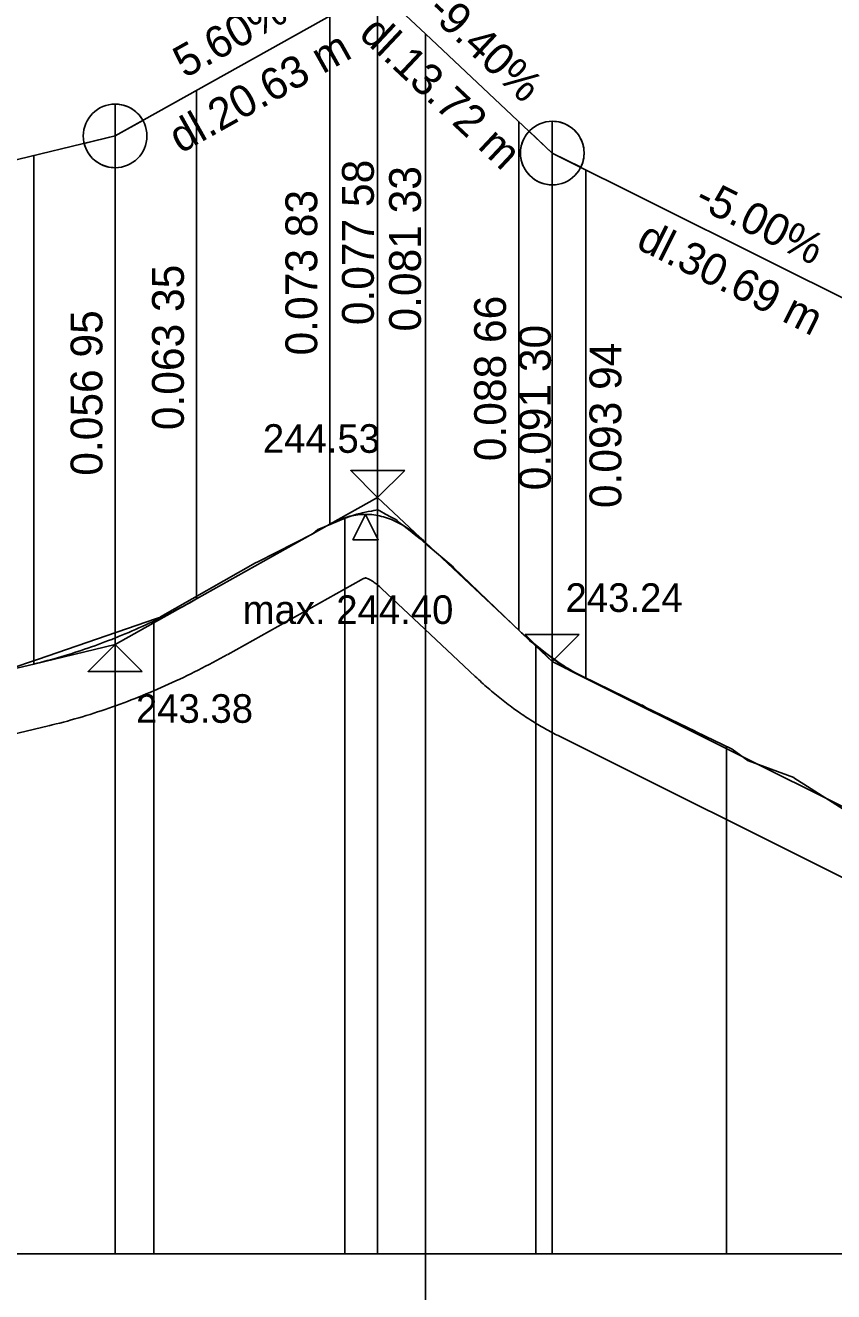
# Model space of a CAD drawing. Extents: x -598463 to -597973, y -1203201 to -1202904.
# Drawn here: x -598289.3 to -598225.8, y -1203056 to -1202956.4 of the extents above; entities that cross this region are included whole.
import ezdxf

# ---------------------------------------------------------------- set-up
doc = ezdxf.new("R2010")
doc.units = 0
for name, color, linetype in [('geom_Pomoc', 7, 'Continuous'), ('profil_popis', 7, 'Continuous'), ('profil_popis_niveleta', 7, 'Continuous'), ('rez_teren', 7, 'Continuous')]:
    doc.layers.add(name, color=color, linetype=linetype)

msp = doc.modelspace()

# ---------------------------------------------------------------- linework, layer by layer
at = {"layer": 'geom_Pomoc'}
for p, q in [((-598257.882, -1202997.029), (-598257.883, -1203138.847)), ((-598339.213, -1203052.987), (-598207.733, -1203052.987))]:
    msp.add_line(p, q, dxfattribs=at)
at = {"layer": 'profil_popis'}
for p, q in [((-598261.632, -1202953.504), (-598261.632, -1203052.987)), ((-598282.262, -1202965.057), (-598282.262, -1203052.987))]:
    msp.add_line(p, q, dxfattribs=at)
for points in [[(-598264.213, -1202995.131), (-598264.213, -1203052.987)], [(-598279.213, -1203003.087), (-598279.213, -1203052.987)], [(-598249.213, -1203005.1), (-598249.213, -1203052.987)], [(-598247.908, -1203005.1), (-598247.908, -1203052.987)], [(-598234.213, -1203013.077), (-598234.213, -1203052.987)]]:
    msp.add_lwpolyline(points, dxfattribs=at)
at = {"layer": 'profil_popis_niveleta'}
for p, q in [((-598282.262, -1202965.057), (-598261.632, -1202953.504)), ((-598261.632, -1202953.504), (-598261.632, -1202993.504)), ((-598261.632, -1202953.504), (-598257.882, -1202957.029)), ((-598265.382, -1202995.604), (-598265.382, -1202955.604)), ((-598257.882, -1202997.029), (-598257.882, -1202957.029)), ((-598257.882, -1202957.029), (-598247.908, -1202966.404)), ((-598275.862, -1203001.473), (-598275.862, -1202961.473)), ((-598250.548, -1203003.922), (-598250.548, -1202963.922)), ((-598316.917, -1202973.374), (-598282.262, -1202965.057)), ((-598282.262, -1202965.057), (-598282.262, -1203005.057)), ((-598288.662, -1203006.593), (-598288.662, -1202966.593)), ((-598247.908, -1202966.404), (-598247.908, -1203006.404)), ((-598247.908, -1202966.404), (-598217.22, -1202981.748)), ((-598245.268, -1203007.724), (-598245.268, -1202967.724)), ((-598265.382, -1202995.604), (-598261.632, -1202993.504)), ((-598261.632, -1202993.504), (-598257.882, -1202997.029)), ((-598275.862, -1203001.473), (-598265.382, -1202995.604)), ((-598257.882, -1202997.029), (-598250.548, -1203003.922)), ((-598273.419, -1203005.835), (-598262.939, -1202999.966)), ((-598261.306, -1203000.672), (-598258.361, -1203003.441)), ((-598282.262, -1203005.057), (-598275.862, -1203001.473)), ((-598258.361, -1203003.441), (-598253.973, -1203007.565)), ((-598250.548, -1203003.922), (-598247.908, -1203006.404)), ((-598288.662, -1203006.593), (-598282.262, -1203005.057)), ((-598301.717, -1203009.726), (-598288.662, -1203006.593)), ((-598247.908, -1203006.404), (-598245.268, -1203007.724)), ((-598245.268, -1203007.724), (-598221.12, -1203019.798)), ((-598300.551, -1203014.588), (-598287.495, -1203011.455)), ((-598247.504, -1203012.196), (-598223.356, -1203024.27))]:
    msp.add_line(p, q, dxfattribs=at)
for points in [[(-598282.262, -1202965.057), (-598282.262, -1202962.557), (-598282.102, -1202962.562), (-598281.942, -1202962.577), (-598281.784, -1202962.603), (-598281.628, -1202962.638), (-598281.474, -1202962.684), (-598281.324, -1202962.739), (-598281.177, -1202962.804), (-598281.035, -1202962.878), (-598280.898, -1202962.961), (-598280.767, -1202963.053), (-598280.641, -1202963.153), (-598280.523, -1202963.261), (-598280.411, -1202963.376), (-598280.307, -1202963.498), (-598280.212, -1202963.626), (-598280.124, -1202963.761), (-598280.081, -1202963.835), (-598282.262, -1202965.057), (-598282.262, -1202967.557), (-598282.422, -1202967.551), (-598282.582, -1202967.536), (-598282.74, -1202967.511), (-598282.896, -1202967.475), (-598283.05, -1202967.429), (-598283.2, -1202967.374), (-598283.347, -1202967.309), (-598283.489, -1202967.235), (-598283.626, -1202967.152), (-598283.757, -1202967.06), (-598283.883, -1202966.96), (-598284.001, -1202966.852), (-598284.113, -1202966.737), (-598284.217, -1202966.615), (-598284.312, -1202966.487), (-598284.4, -1202966.353), (-598284.479, -1202966.213), (-598284.548, -1202966.069), (-598284.608, -1202965.92), (-598284.659, -1202965.768), (-598284.693, -1202965.64)], [(-598247.908, -1202966.404), (-598247.908, -1202963.904), (-598247.748, -1202963.909), (-598247.588, -1202963.924), (-598247.43, -1202963.95), (-598247.274, -1202963.986), (-598247.12, -1202964.031), (-598246.97, -1202964.086), (-598246.823, -1202964.151), (-598246.681, -1202964.225), (-598246.544, -1202964.309), (-598246.413, -1202964.4), (-598246.287, -1202964.5), (-598246.169, -1202964.608), (-598246.057, -1202964.723), (-598245.953, -1202964.845), (-598245.858, -1202964.973), (-598245.77, -1202965.108), (-598245.692, -1202965.247), (-598245.622, -1202965.392), (-598245.562, -1202965.54), (-598245.511, -1202965.692), (-598245.471, -1202965.847), (-598245.44, -1202966.005), (-598245.42, -1202966.164), (-598245.409, -1202966.324), (-598245.409, -1202966.484), (-598245.42, -1202966.644), (-598245.44, -1202966.803), (-598245.471, -1202966.96), (-598245.511, -1202967.115), (-598245.562, -1202967.267), (-598245.622, -1202967.416), (-598245.672, -1202967.522), (-598247.908, -1202966.404), (-598247.908, -1202968.904), (-598248.068, -1202968.899), (-598248.228, -1202968.883), (-598248.386, -1202968.858), (-598248.542, -1202968.822), (-598248.696, -1202968.776), (-598248.846, -1202968.721), (-598248.993, -1202968.656), (-598249.135, -1202968.582), (-598249.272, -1202968.499), (-598249.403, -1202968.407), (-598249.529, -1202968.307), (-598249.647, -1202968.2), (-598249.759, -1202968.085), (-598249.863, -1202967.963), (-598249.958, -1202967.834), (-598250.046, -1202967.7), (-598250.125, -1202967.56), (-598250.194, -1202967.416), (-598250.254, -1202967.267), (-598250.305, -1202967.115), (-598250.345, -1202966.96), (-598250.376, -1202966.803), (-598250.397, -1202966.644), (-598250.407, -1202966.484), (-598250.407, -1202966.324), (-598250.397, -1202966.164), (-598250.376, -1202966.005), (-598250.345, -1202965.847), (-598250.305, -1202965.692), (-598250.254, -1202965.54), (-598250.194, -1202965.392), (-598250.125, -1202965.247), (-598250.046, -1202965.108), (-598249.958, -1202964.973), (-598249.863, -1202964.845), (-598249.759, -1202964.723), (-598249.73, -1202964.692)], [(-598262.582, -1202994.819), (-598263.582, -1202996.819), (-598261.582, -1202996.819)]]:
    msp.add_lwpolyline(points, close=True, dxfattribs=at)
for points in [[(-598261.632, -1202993.504), (-598263.753, -1202991.382), (-598259.51, -1202991.382)], [(-598259.51, -1202991.382), (-598261.632, -1202993.504)], [(-598265.382, -1202995.604), (-598265.225, -1202995.519), (-598265.069, -1202995.438), (-598264.913, -1202995.363), (-598264.757, -1202995.293), (-598264.6, -1202995.227), (-598264.444, -1202995.166), (-598264.288, -1202995.111), (-598264.132, -1202995.06), (-598263.975, -1202995.014), (-598263.819, -1202994.973), (-598263.663, -1202994.937), (-598263.507, -1202994.905), (-598263.35, -1202994.879), (-598263.194, -1202994.857), (-598263.038, -1202994.84), (-598262.882, -1202994.829), (-598262.725, -1202994.822), (-598262.569, -1202994.82), (-598262.413, -1202994.822), (-598262.257, -1202994.83), (-598262.1, -1202994.843), (-598261.944, -1202994.86), (-598261.788, -1202994.883), (-598261.475, -1202994.942), (-598261.319, -1202994.979), (-598261.163, -1202995.021), (-598261.007, -1202995.068), (-598260.85, -1202995.119), (-598260.694, -1202995.176), (-598260.538, -1202995.237), (-598260.382, -1202995.304), (-598260.225, -1202995.375), (-598260.069, -1202995.451), (-598259.913, -1202995.532), (-598259.757, -1202995.618), (-598259.6, -1202995.708), (-598259.444, -1202995.804), (-598259.288, -1202995.904), (-598259.132, -1202996.01), (-598258.975, -1202996.12), (-598258.819, -1202996.235), (-598258.663, -1202996.355), (-598258.507, -1202996.48), (-598258.35, -1202996.61), (-598258.194, -1202996.745), (-598258.038, -1202996.884), (-598257.882, -1202997.029)], [(-598262.991, -1202999.995), (-598262.888, -1202999.939), (-598262.842, -1202999.915), (-598262.8, -1202999.895), (-598262.762, -1202999.878), (-598262.729, -1202999.864), (-598262.699, -1202999.853), (-598262.673, -1202999.843), (-598262.651, -1202999.836), (-598262.633, -1202999.831), (-598262.618, -1202999.827), (-598262.606, -1202999.824), (-598262.597, -1202999.822), (-598262.591, -1202999.821), (-598262.586, -1202999.821), (-598262.585, -1202999.821), (-598262.529, -1202999.831), (-598262.528, -1202999.832), (-598262.509, -1202999.837), (-598262.486, -1202999.845), (-598262.46, -1202999.854), (-598262.43, -1202999.866), (-598262.395, -1202999.881), (-598262.357, -1202999.898), (-598262.314, -1202999.919), (-598262.267, -1202999.943), (-598262.216, -1202999.971), (-598262.161, -1203000.003), (-598262.102, -1203000.04), (-598262.038, -1203000.08), (-598261.971, -1203000.126), (-598261.9, -1203000.176), (-598261.825, -1203000.231), (-598261.747, -1203000.291), (-598261.665, -1203000.356), (-598261.58, -1203000.427), (-598261.492, -1203000.503), (-598261.4, -1203000.585), (-598261.276, -1203000.7)], [(-598288.662, -1203006.593), (-598288.395, -1203006.528), (-598288.129, -1203006.461), (-598287.862, -1203006.393), (-598287.595, -1203006.322), (-598287.329, -1203006.25), (-598287.062, -1203006.177), (-598286.795, -1203006.101), (-598286.529, -1203006.024), (-598286.262, -1203005.945), (-598285.995, -1203005.864), (-598285.729, -1203005.781), (-598285.462, -1203005.697), (-598285.195, -1203005.61), (-598284.929, -1203005.522), (-598284.662, -1203005.433), (-598284.395, -1203005.341), (-598284.129, -1203005.248), (-598283.862, -1203005.153), (-598283.595, -1203005.056), (-598283.329, -1203004.957), (-598283.062, -1203004.857), (-598282.795, -1203004.754), (-598282.529, -1203004.65), (-598281.995, -1203004.437), (-598281.729, -1203004.328), (-598281.462, -1203004.217), (-598281.195, -1203004.104), (-598280.929, -1203003.989), (-598280.662, -1203003.873), (-598280.395, -1203003.754), (-598280.129, -1203003.634), (-598279.862, -1203003.513), (-598279.595, -1203003.389), (-598279.329, -1203003.264), (-598279.062, -1203003.137), (-598278.795, -1203003.008), (-598278.529, -1203002.877), (-598278.262, -1203002.745), (-598277.995, -1203002.61), (-598277.729, -1203002.474), (-598277.462, -1203002.337), (-598277.195, -1203002.197), (-598276.929, -1203002.056), (-598276.662, -1203001.913), (-598276.395, -1203001.768), (-598276.129, -1203001.621), (-598275.862, -1203001.473)], [(-598250.548, -1203003.922), (-598250.438, -1203004.025), (-598250.328, -1203004.127), (-598250.218, -1203004.228), (-598250.108, -1203004.328), (-598249.998, -1203004.427), (-598249.888, -1203004.524), (-598249.778, -1203004.621), (-598249.668, -1203004.717), (-598249.558, -1203004.812), (-598249.448, -1203004.906), (-598249.338, -1203004.999), (-598249.228, -1203005.09), (-598249.118, -1203005.181), (-598249.008, -1203005.271), (-598248.898, -1203005.36), (-598248.788, -1203005.448), (-598248.678, -1203005.534), (-598248.568, -1203005.62), (-598248.458, -1203005.705), (-598248.348, -1203005.789), (-598248.238, -1203005.871), (-598248.128, -1203005.953), (-598248.018, -1203006.034), (-598247.798, -1203006.192), (-598247.688, -1203006.27), (-598247.578, -1203006.346), (-598247.468, -1203006.422), (-598247.358, -1203006.497), (-598247.248, -1203006.57), (-598247.138, -1203006.643), (-598247.028, -1203006.715), (-598246.918, -1203006.785), (-598246.808, -1203006.855), (-598246.698, -1203006.924), (-598246.588, -1203006.991), (-598246.478, -1203007.058), (-598246.368, -1203007.123), (-598246.258, -1203007.188), (-598246.148, -1203007.252), (-598246.038, -1203007.314), (-598245.928, -1203007.376), (-598245.818, -1203007.436), (-598245.708, -1203007.496), (-598245.598, -1203007.554), (-598245.488, -1203007.612), (-598245.378, -1203007.668), (-598245.268, -1203007.724)], [(-598247.908, -1203006.404), (-598250.029, -1203004.282), (-598245.787, -1203004.282)], [(-598245.787, -1203004.282), (-598247.908, -1203006.404)], [(-598282.262, -1203005.057), (-598284.383, -1203007.178), (-598280.141, -1203007.178)], [(-598280.141, -1203007.178), (-598282.262, -1203005.057)], [(-598287.48, -1203011.451), (-598287.198, -1203011.382), (-598286.901, -1203011.308), (-598286.604, -1203011.232), (-598286.307, -1203011.154), (-598286.01, -1203011.073), (-598285.714, -1203010.991), (-598285.418, -1203010.907), (-598285.121, -1203010.822), (-598284.825, -1203010.734), (-598284.529, -1203010.644), (-598284.234, -1203010.552), (-598283.938, -1203010.459), (-598283.643, -1203010.363), (-598283.348, -1203010.266), (-598283.053, -1203010.166), (-598282.758, -1203010.065), (-598282.463, -1203009.962), (-598282.168, -1203009.857), (-598281.874, -1203009.75), (-598281.58, -1203009.641), (-598281.286, -1203009.531), (-598280.992, -1203009.418), (-598280.692, -1203009.301), (-598280.118, -1203009.071), (-598279.819, -1203008.949), (-598279.526, -1203008.827), (-598279.233, -1203008.703), (-598278.941, -1203008.577), (-598278.648, -1203008.449), (-598278.356, -1203008.32), (-598278.064, -1203008.188), (-598277.773, -1203008.055), (-598277.481, -1203007.92), (-598277.19, -1203007.783), (-598276.898, -1203007.644), (-598276.607, -1203007.504), (-598276.317, -1203007.361), (-598276.026, -1203007.217), (-598275.736, -1203007.071), (-598275.445, -1203006.923), (-598275.155, -1203006.773), (-598274.865, -1203006.621), (-598274.576, -1203006.468), (-598274.286, -1203006.312), (-598273.997, -1203006.155), (-598273.708, -1203005.996), (-598273.43, -1203005.841)], [(-598253.964, -1203007.574), (-598253.845, -1203007.685), (-598253.717, -1203007.804), (-598253.588, -1203007.921), (-598253.46, -1203008.038), (-598253.331, -1203008.154), (-598253.202, -1203008.269), (-598253.072, -1203008.383), (-598252.943, -1203008.496), (-598252.813, -1203008.608), (-598252.683, -1203008.719), (-598252.552, -1203008.829), (-598252.421, -1203008.938), (-598252.29, -1203009.046), (-598252.159, -1203009.153), (-598252.027, -1203009.259), (-598251.896, -1203009.365), (-598251.763, -1203009.469), (-598251.631, -1203009.572), (-598251.498, -1203009.674), (-598251.365, -1203009.776), (-598251.232, -1203009.876), (-598251.098, -1203009.975), (-598250.958, -1203010.078), (-598250.701, -1203010.263), (-598250.56, -1203010.363), (-598250.425, -1203010.457), (-598250.289, -1203010.55), (-598250.153, -1203010.643), (-598250.017, -1203010.734), (-598249.88, -1203010.824), (-598249.743, -1203010.913), (-598249.606, -1203011.002), (-598249.468, -1203011.089), (-598249.33, -1203011.175), (-598249.192, -1203011.26), (-598249.053, -1203011.344), (-598248.914, -1203011.427), (-598248.775, -1203011.508), (-598248.635, -1203011.589), (-598248.495, -1203011.669), (-598248.354, -1203011.747), (-598248.214, -1203011.825), (-598248.072, -1203011.901), (-598247.931, -1203011.977), (-598247.789, -1203012.051), (-598247.647, -1203012.124), (-598247.52, -1203012.188)]]:
    msp.add_lwpolyline(points, dxfattribs=at)
for centre in [(-598282.262, -1202965.057), (-598247.908, -1202966.404)]:
    msp.add_circle(centre, 2.5, dxfattribs=at)
at = {"layer": 'rez_teren'}
msp.add_lwpolyline([(-598290.526, -1203006.981), (-598288.375, -1203006.24), (-598279.012, -1203003.018), (-598278.704, -1203002.916), (-598278.69, -1203002.876), (-598278.69, -1203002.876), (-598271.219, -1202998.64), (-598271.055, -1202998.547), (-598266.735, -1202996.36), (-598266.326, -1202996.003), (-598265.808, -1202995.799), (-598264.632, -1202995.3), (-598264.18, -1202995.118), (-598263.728, -1202994.956), (-598263.276, -1202994.815), (-598262.824, -1202994.696), (-598262.372, -1202994.6), (-598262.111, -1202994.559), (-598262.11, -1202994.559), (-598262.106, -1202994.556), (-598261.92, -1202994.512), (-598261.631, -1202994.454), (-598261.625, -1202994.454), (-598261.468, -1202994.546), (-598261.016, -1202994.803), (-598260.564, -1202995.051), (-598260.211, -1202995.235), (-598260.112, -1202995.301), (-598260.095, -1202995.312), (-598260.095, -1202995.312), (-598260.03, -1202995.383), (-598260.03, -1202995.383), (-598260.014, -1202995.396), (-598259.66, -1202995.658), (-598259.208, -1202996.009), (-598258.756, -1202996.374), (-598258.304, -1202996.748), (-598257.852, -1202997.13), (-598255.683, -1202998.972), (-598255.683, -1202998.972), (-598255.663, -1202998.988), (-598249.688, -1203004.735), (-598249.54, -1203004.868), (-598249.54, -1203004.868), (-598249.367, -1203004.978), (-598248.197, -1203005.905), (-598246.962, -1203006.858), (-598246.957, -1203006.862), (-598246.888, -1203006.913), (-598246.85, -1203006.937), (-598246.746, -1203006.974), (-598241.015, -1203009.775), (-598240.897, -1203009.822), (-598240.883, -1203009.876), (-598240.879, -1203009.879), (-598240.839, -1203009.819), (-598240.815, -1203009.824), (-598240.557, -1203010), (-598236.675, -1203011.875), (-598236.598, -1203011.914), (-598233.826, -1203013.266), (-598233.806, -1203013.284), (-598233.78, -1203013.294), (-598232.515, -1203014.196), (-598232.513, -1203014.196), (-598232.509, -1203014.188), (-598232.499, -1203014.194), (-598228.935, -1203015.528), (-598228.932, -1203015.529), (-598228.932, -1203015.529), (-598228.924, -1203015.534), (-598225.924, -1203017.458), (-598225.92, -1203017.461), (-598224.264, -1203018.502)], dxfattribs=at)

# ---------------------------------------------------------------- texts
at = {"layer": 'profil_popis_niveleta'}
for s, height, rotation, p in [('5.60%', 2.5, 29.24883, (-598276.782, -1202960.555)), ('-9.40%', 2.5, 316.77147, (-598257.865, -1202955.329)), ('dl.13.72 m', 2.5, 316.77147, (-598263.197, -1202957.179)), ('dl.20.63 m', 2.5, 29.24883, (-598277.13, -1202966.48)), ('0.077 58', 2.5, 90, (-598261.933, -1202979.942)), ('0.081 33', 2.5, 90, (-598258.23, -1202980.44)), ('0.073 83', 2.5, 90, (-598266.382, -1202982.319)), ('-5.00%', 2.5, 333.43495, (-598236.856, -1202970.532)), ('dl.30.69 m', 2.5, 333.43495, (-598241.433, -1202973.834)), ('0.063 35', 2.5, 90, (-598276.862, -1202988.198)), ('0.088 66', 2.5, 90, (-598251.548, -1202990.638)), ('0.056 95', 2.5, 90, (-598283.262, -1202991.782)), ('0.091 30', 2.5, 90, (-598248.03, -1202992.929)), ('0.093 94', 2.5, 90, (-598242.484, -1202994.328)), ('244.53', 2.25, 360, (-598270.65, -1202989.98)), ('243.24', 2.25, 360, (-598246.869, -1203002.492)), ('max. 244.40', 2.25, 360, (-598272.239, -1203003.441)), ('243.38', 2.25, 360, (-598280.627, -1203011.216))]:
    msp.add_text(s, height=height, rotation=rotation, dxfattribs=at).set_placement(p)

doc.saveas('drawing.dxf')
